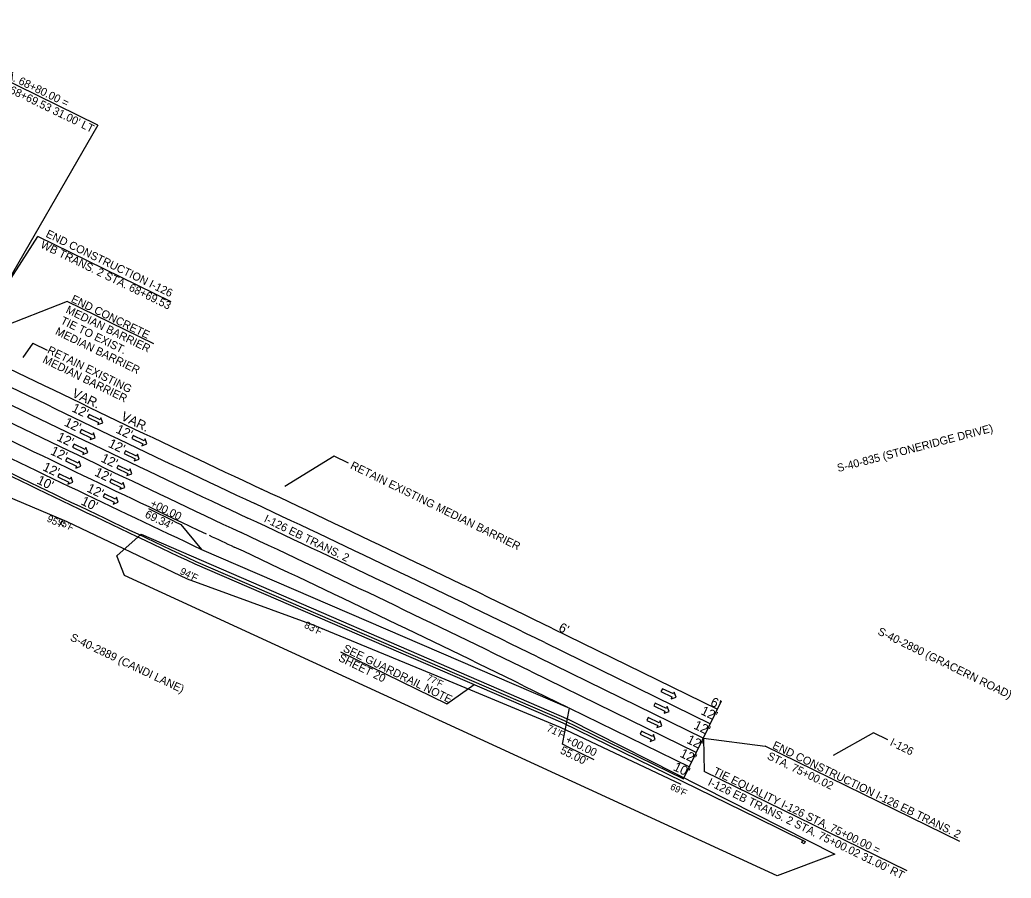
# Model space of a CAD drawing. Extents: x 1966090 to 1975830, y 788086 to 801233.
# Drawn here: x 1974136 to 1974879, y 793639 to 794283 of the extents above; entities that cross this region are included whole.
import ezdxf

# ---------------------------------------------------------------- set-up
doc = ezdxf.new("R2010")
doc.units = 0
for name, color, linetype in [('BR_PRESTRESSED BEAM', 7, 'Continuous'), ('BR_PROPOSED_DRAINAGE', 7, 'Continuous'), ('RD_EX_Driveway_txCode', 7, 'Continuous'), ('RD_EX_RW_TX', 7, 'Continuous'), ('RD_EX_SU_Gas', 7, 'Continuous'), ('RD_EX_SU_SwpLmt', 7, 'Continuous'), ('RD_PD_PaveShd', 7, 'Continuous'), ('RD_Sketch6', 7, 'Continuous'), ('RD_Sketch8', 7, 'Continuous')]:
    doc.layers.add(name, color=color, linetype=linetype)

msp = doc.modelspace()

# ---------------------------------------------------------------- linework, layer by layer
at = {"layer": 'BR_PRESTRESSED BEAM'}
for p, q in [((1974266.69, 793874.68), (1974542.52, 793755.58)), ((1974542.52, 793755.58), (1974688.28, 793684.21)), ((1974688.28, 793684.21), (1974724.21, 793666.62)), ((1974721.53, 793665.7), (1974722.41, 793667.5)), ((1974722.41, 793667.5), (1974724.21, 793666.62)), ((1974724.21, 793666.62), (1974723.33, 793664.82)), ((1974723.33, 793664.82), (1974721.53, 793665.7))]:
    msp.add_line(p, q, dxfattribs=at)
msp.add_arc((1980465.89, 807035.77), 14548, 243.911196, 244.778393, dxfattribs=at)
at = {"layer": 'BR_PROPOSED_DRAINAGE'}
for p, q in [((1974078.33, 793945.2), (1974170.74, 793906.55)), ((1974170.74, 793906.55), (1974260.93, 793863.34)), ((1974260.93, 793863.34), (1974355.51, 793829.09)), ((1974355.51, 793829.09), (1974448.06, 793790.72)), ((1974448.06, 793790.72), (1974540.61, 793752.34)), ((1974540.61, 793752.34), (1974630.98, 793709.49))]:
    msp.add_line(p, q, dxfattribs=at)
at = {"layer": 'RD_EX_Driveway_txCode'}
for points in [[(1974187.4, 793986.77), (1974186.36, 793984.61), (1974194.61, 793980.61), (1974193.9, 793979.15), (1974197.68, 793980.46), (1974196.37, 793984.24), (1974195.66, 793982.77)], [(1974181.68, 793975.43), (1974180.64, 793973.27), (1974188.89, 793969.27), (1974188.18, 793967.8), (1974191.96, 793969.11), (1974190.65, 793972.89), (1974189.94, 793971.43)], [(1974176.16, 793964.4), (1974175.11, 793962.24), (1974183.37, 793958.24), (1974182.66, 793956.77), (1974186.44, 793958.08), (1974185.13, 793961.86), (1974184.42, 793960.4)], [(1974220.44, 793970.86), (1974219.39, 793968.7), (1974227.65, 793964.7), (1974226.94, 793963.23), (1974230.72, 793964.54), (1974229.41, 793968.32), (1974228.7, 793966.86)], [(1974214.72, 793959.51), (1974213.68, 793957.35), (1974221.93, 793953.35), (1974221.22, 793951.89), (1974225, 793953.2), (1974223.69, 793956.98), (1974222.98, 793955.51)], [(1974170.93, 793954.11), (1974169.89, 793951.95), (1974178.14, 793947.95), (1974177.43, 793946.49), (1974181.21, 793947.8), (1974179.9, 793951.58), (1974179.19, 793950.11)], [(1974165.07, 793942.12), (1974164.02, 793939.96), (1974172.27, 793935.96), (1974171.56, 793934.5), (1974175.34, 793935.81), (1974174.03, 793939.59), (1974173.32, 793938.12)], [(1974209.2, 793948.48), (1974208.15, 793946.32), (1974216.41, 793942.32), (1974215.7, 793940.86), (1974219.48, 793942.17), (1974218.16, 793945.95), (1974217.45, 793944.48)], [(1974203.97, 793938.2), (1974202.93, 793936.04), (1974211.18, 793932.04), (1974210.47, 793930.57), (1974214.25, 793931.88), (1974212.94, 793935.66), (1974212.23, 793934.2)], [(1974199.05, 793927.15), (1974198.01, 793924.99), (1974206.26, 793920.99), (1974205.55, 793919.53), (1974209.33, 793920.84), (1974208.02, 793924.62), (1974207.31, 793923.15)], [(1974617.1, 793781.09), (1974616.06, 793778.93), (1974624.33, 793774.95), (1974623.62, 793773.49), (1974627.4, 793774.81), (1974626.07, 793778.58), (1974625.37, 793777.12)], [(1974611.82, 793770.31), (1974610.78, 793768.15), (1974619.05, 793764.18), (1974618.35, 793762.71), (1974622.12, 793764.03), (1974620.8, 793767.81), (1974620.09, 793766.34)], [(1974606.55, 793759.54), (1974605.51, 793757.37), (1974613.77, 793753.4), (1974613.07, 793751.93), (1974616.84, 793753.26), (1974615.52, 793757.03), (1974614.81, 793755.56)], [(1974601.49, 793749.2), (1974600.45, 793747.04), (1974608.71, 793743.06), (1974608.01, 793741.6), (1974611.78, 793742.92), (1974610.46, 793746.69), (1974609.75, 793745.23)]]:
    msp.add_lwpolyline(points, close=True, dxfattribs=at)
at = {"layer": 'RD_EX_SU_Gas'}
for p, q in [((1974528.93, 793815.69), (1974653.18, 793754.84)), ((1974523.65, 793804.91), (1974647.91, 793744.07)), ((1974518.37, 793794.13), (1974642.63, 793733.29)), ((1974513.1, 793783.35), (1974546.14, 793767.17))]:
    msp.add_line(p, q, dxfattribs=at)
for centre, radius, start, end in [((1980465.89, 807035.77), 14488, 243.911196, 244.862838), ((1980465.89, 807035.77), 14500, 243.911196, 244.862838), ((1980465.89, 807035.77), 14512, 243.911196, 244.862838), ((1980465.89, 807035.77), 14524, 243.911196, 244.771344), ((1968147.08, 780782.26), 14512, 63.911196, 64.862838), ((1968147.08, 780782.26), 14500, 63.911196, 64.862838), ((1968147.08, 780782.26), 14488, 63.911196, 64.862838), ((1980465.89, 807035.77), 14524, 244.780512, 244.862838), ((1968147.08, 780782.26), 14476, 63.911196, 64.862838)]:
    msp.add_arc(centre, radius, start, end, dxfattribs=at)
at = {"layer": 'RD_PD_PaveShd'}
for p, q in [((1974267.54, 793876.49), (1974543.58, 793757.31)), ((1974543.14, 793757.51), (1974632.95, 793713.53))]:
    msp.add_line(p, q, dxfattribs=at)
msp.add_arc((1980465.89, 807035.77), 14546, 243.911196, 244.778392, dxfattribs=at)
at = {"layer": 'RD_Sketch6'}
for p, q in [((1974193.95, 794203.67), (1974044.61, 794276.8)), ((1974193.95, 794203.67), (1974118.34, 794072.4)), ((1974118.34, 794072.4), (1974148.93, 794120.19)), ((1974249.06, 794071.16), (1974148.93, 794120.19)), ((1974170.91, 794071.49), (1974105.15, 794045.46)), ((1974235.92, 794039.66), (1974170.91, 794071.49)), ((1974145.19, 794040.2), (1974137.81, 794029.47)), ((1974145.19, 794040.2), (1974155.96, 794034.92)), ((1974371.18, 793955.47), (1974334.25, 793932.65)), ((1974381.96, 793950.19), (1974371.18, 793955.47)), ((1974251.54, 793906.41), (1974232.14, 793915.91)), ((1974375.85, 793808.72), (1974455.5, 793769.72)), ((1974455.5, 793769.72), (1974476.1, 793784.26)), ((1974647.91, 793744.07), (1974648.43, 793719.06)), ((1974647.91, 793744.07), (1974694.11, 793738)), ((1974775.33, 793748.02), (1974745.07, 793731.01)), ((1974786.11, 793742.74), (1974775.33, 793748.02)), ((1974565.89, 793727.86), (1974546.5, 793737.36)), ((1974840.16, 793666.49), (1974694.11, 793738)), ((1974800.69, 793644.51), (1974648.43, 793719.06))]:
    msp.add_line(p, q, dxfattribs=at)
for points in [[(1974251.54, 793906.41), (1974256.16, 793904.16), (1974271.8, 793885.54)], [(1974546.5, 793737.36), (1974542.26, 793739.44), (1974547.54, 793766.49)]]:
    msp.add_lwpolyline(points, dxfattribs=at)
msp.add_lwpolyline([(1974208.17, 793880.69), (1974226.45, 793896.97), (1974547, 793758.11), (1974746.38, 793657.02), (1974703.26, 793640.89), (1974214.11, 793866.02)], close=True, dxfattribs=at)
at = {"layer": 'RD_Sketch8'}
for p, q in [((1974271.8, 793885.54), (1974547.54, 793766.49)), ((1974534.2, 793826.46), (1974658.46, 793765.62)), ((1974632.95, 793713.53), (1974661.54, 793771.91)), ((1974547.54, 793766.49), (1974637.35, 793722.51))]:
    msp.add_line(p, q, dxfattribs=at)
for centre, radius, start, end in [((1980465.89, 807035.77), 14476, 243.911196, 244.862838), ((1980465.89, 807035.77), 14536, 243.911196, 244.778392), ((1968147.08, 780782.26), 14524, 63.911196, 64.862838)]:
    msp.add_arc(centre, radius, start, end, dxfattribs=at)

# ---------------------------------------------------------------- texts
at = {"layer": 'RD_EX_Driveway_txCode'}
for s, height, rotation, p in [('VAR.', 7, 334.14444, (1974174.04, 794000.39)), ("12'", 7, 334.14444, (1974173.9, 793989.22)), ('VAR.', 7, 334.14444, (1974210.77, 793982.96)), ("12'", 7, 334.14444, (1974168.23, 793978.54)), ("12'", 7, 334.14444, (1974206.94, 793973.3)), ('S-40-835 (STONERIDGE DRIVE)', 5.9996, 14.61655, (1974748.94, 793943.46)), ("12'", 7, 334.14444, (1974162.71, 793967.51)), ("12'", 7, 334.14444, (1974201.27, 793962.62)), ("12'", 7, 334.14444, (1974157.98, 793957.02)), ("12'", 7, 334.14444, (1974195.75, 793951.59)), ("12'", 7, 334.14444, (1974152.11, 793945.04)), ("12'", 7, 334.14444, (1974191.02, 793941.11)), ("10'", 7, 334.14444, (1974147.71, 793935.2)), ("12'", 7, 334.14444, (1974185.15, 793929.12)), ("10'", 7, 334.14444, (1974180.81, 793919.46)), ("6'", 7, 334.14444, (1974538.73, 793824.66)), ('S-40-2890 (GRACERN ROAD)', 5.9996, 333.88401, (1974777.94, 793822.05)), ('S-40-2889 (CANDI LANE)', 5.9996, 334.64514, (1974172.77, 793817.54)), ("6'", 7, 334.32621, (1974652.49, 793768.79)), ("12'", 7, 334.32458, (1974645.32, 793762.19)), ("12'", 7, 334.32458, (1974640.04, 793751.41)), ("12'", 7, 334.32458, (1974634.76, 793740.64)), ("12'", 7, 334.32458, (1974629.7, 793730.3)), ("10'", 7, 334.32621, (1974624.75, 793720.2))]:
    msp.add_text(s, height=height, rotation=rotation, dxfattribs=at).set_placement(p)
at = {"layer": 'RD_EX_RW_TX'}
for s, p in [("95'F", (1974163.13, 793904.71)), ("77'F", (1974439.84, 793787.64)), ("69'F", (1974622.51, 793705.92))]:
    msp.add_text(s, height=5, rotation=333.9112, dxfattribs=at).set_placement(p)
at = {"layer": 'RD_EX_SU_SwpLmt'}
for s, p in [("95'F", (1974155.34, 793906.82)), ("94'F", (1974255.02, 793867.32)), ("83'F", (1974348.17, 793827.06)), ("71'F", (1974529.93, 793749.64))]:
    msp.add_text(s, height=5.4, rotation=333.9112, dxfattribs=at).set_placement(p)
at = {"layer": 'RD_Sketch6'}
for s, height, rotation, p in [('TIE EQUALITY I-126 STA. 68+80.00 =', 5.9996, 334.0727, (1974046.57, 794277.22)), ("I-126 WB TRANS. 2 STA. 68+69.53 31.00' LT", 5.9996, 334.0727, (1974042.63, 794269.13)), ('END CONSTRUCTION I-126', 5.9996, 334.0727, (1974154.47, 794120.08)), ('WB TRANS. 2 STA. 68+69.53', 5.9996, 334.0727, (1974150.54, 794111.98)), ('END CONCRETE', 5.9996, 334.0727, (1974173.42, 794071.28)), ('MEDIAN BARRIER', 5.9996, 334.0727, (1974169.49, 794063.18)), ('TIE TO EXIST.', 5.9996, 334.0727, (1974165.55, 794055.09)), ('MEDIAN BARRIER', 5.9996, 334.0727, (1974161.62, 794047)), ('RETAIN EXISTING', 5.9996, 333.9112, (1974155.61, 794032.97)), ('MEDIAN BARRIER ', 5.9996, 333.9112, (1974152.15, 794025.91)), ('RETAIN EXISTING MEDIAN BARRIER', 5.9996, 333.9112, (1974382.77, 793946.45)), ('+00.00', 6, 333.9112, (1974232.7, 793917.98)), ("69.34'", 6, 333.9112, (1974228.75, 793909.9)), ('I-126 EB TRANS. 2 ', 5.9996, 334.0727, (1974318.02, 793906.45)), ('SEE GUARDRAIL NOTE', 5.9996, 333.93779, (1974377.26, 793809.33)), ('SHEET 20', 6, 333.93779, (1974373.8, 793802.27)), ('+00.00', 6, 333.9112, (1974543.97, 793740.98)), ('END CONSTRUCTION I-126 EB TRANS. 2', 5.9996, 334.0727, (1974699.08, 793736.73)), ('I-126', 6, 333.9112, (1974787.14, 793738.9)), ("55.00'", 6, 333.9112, (1974540.02, 793732.9)), ('STA. 75+00.02', 5.9996, 334.0727, (1974695.15, 793728.64)), ('TIE EQUALITY I-126 STA. 75+00.00 =', 5.9996, 334.0727, (1974654.69, 793717.18)), ("I-126 EB TRANS. 2 STA. 75+00.02 31.00' RT", 5.9996, 334.0727, (1974650.75, 793709.09))]:
    msp.add_text(s, height=height, rotation=rotation, dxfattribs=at).set_placement(p)

doc.saveas('drawing.dxf')
